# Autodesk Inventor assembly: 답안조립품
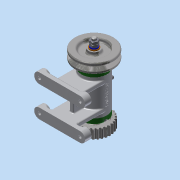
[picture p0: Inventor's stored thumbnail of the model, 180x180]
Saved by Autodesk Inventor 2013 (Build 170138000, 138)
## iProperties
Created: 2015-11
Part Number: 답안조립품
Document SubType Name: Assembly
Designer: a
Author: a
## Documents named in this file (16)
- C:\Users\a\Desktop\451110V1029\답안조립품.iam
- C:\Users\a\Desktop\451110V1029\본체.ipt
- C:\Users\a\Desktop\451110V1029\V벨트풀리.ipt
- C:\Users\a\Desktop\451110V1029\너트 M 8.ipt
- C:\Users\a\Desktop\451110V1029\니플 M 6 x 0.75.ipt
- C:\Users\a\Desktop\451110V1029\베어링 15 x 32 x 9.ipt
- C:\Users\a\Desktop\451110V1029\볼트 M 6 x 8.ipt
- C:\Users\a\Desktop\451110V1029\볼트 M4 x 12.ipt
- C:\Users\a\Desktop\451110V1029\스퍼기어.ipt
- C:\Users\a\Desktop\451110V1029\스프링와셔 8.ipt
- C:\Users\a\Desktop\451110V1029\오일 실 15 25 7.ipt
- C:\Users\a\Desktop\451110V1029\와셔 6x11.5.ipt
- C:\Users\a\Desktop\451110V1029\와셔 8x17.ipt
- C:\Users\a\Desktop\451110V1029\축.ipt
- C:\Users\a\Desktop\451110V1029\커버.ipt
- C:\Users\a\Desktop\451110V1029\키 3 x 3 x 12.ipt
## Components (11 placed, 3 different names)
1. V벨트풀리:1
2. KS B 2023 6002 - 15 x 32 x 9:1
3. KS B 2023 6002 - 15 x 32 x 9:2
4. ISO 4762 M4 x 12:1
5. ISO 4762 M4 x 12:2
6. ISO 4762 M4 x 12:3
7. ISO 4762 M4 x 12:4
8. ISO 4762 M4 x 12:5
9. ISO 4762 M4 x 12:6
10. ISO 4762 M4 x 12:7
11. ISO 4762 M4 x 12:8
